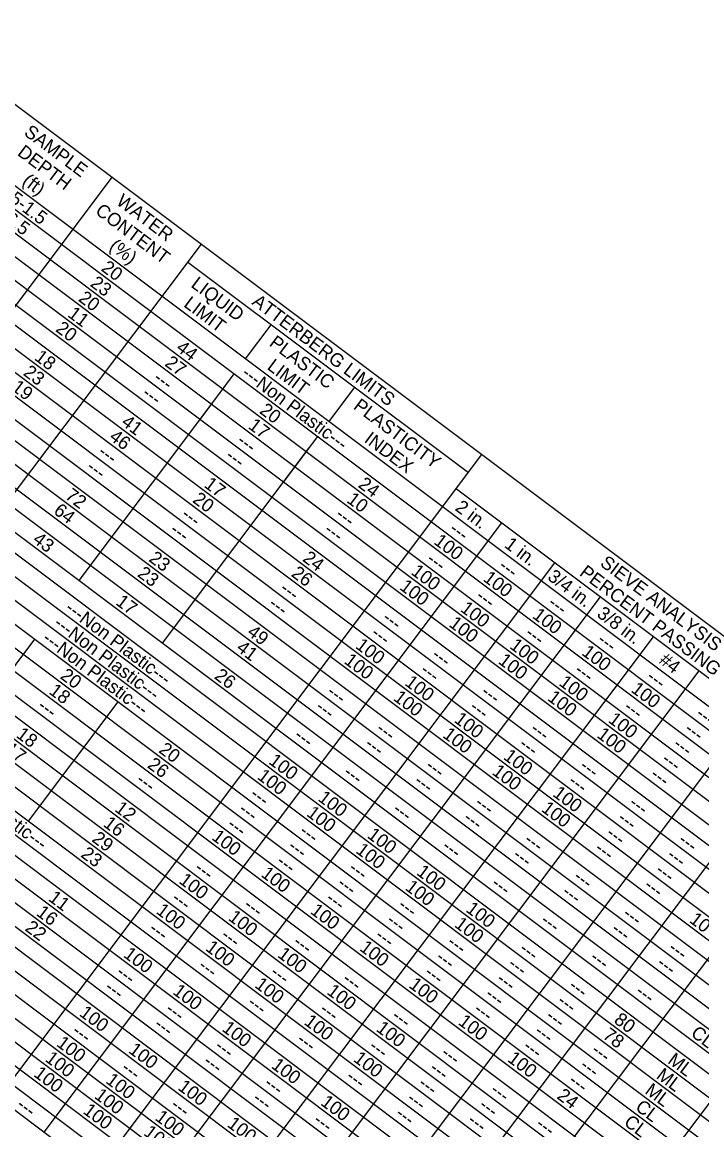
# Model space of a CAD drawing. Extents: x 627484.2 to 627514.4, y 367972.1 to 367996.9.
# Drawn here: x 627494.205 to 627497, y 367987.65 to 367992.209 of the extents above; entities that cross this region are included whole.
import ezdxf

# ---------------------------------------------------------------- set-up
doc = ezdxf.new("R2010")
doc.units = 0
doc.layers.add('Default', color=7, linetype='Continuous')

msp = doc.modelspace()

# ---------------------------------------------------------------- linework, layer by layer
at = {"layer": 'Default'}
for p, q in [((627493.1098, 367992.6713), (627498.3493, 367988.737)), ((627492.9488, 367992.4569), (627498.1883, 367988.5226)), ((627492.902, 367992.3945), (627498.1414, 367988.4602)), ((627492.8552, 367992.3322), (627498.0946, 367988.3978)), ((627492.8083, 367992.2698), (627498.0477, 367988.3355)), ((627492.7615, 367992.2074), (627498.0009, 367988.2731)), ((627492.7147, 367992.1451), (627497.9541, 367988.2107)), ((627492.6737, 367992.0905), (627497.9131, 367988.1562)), ((627492.6268, 367992.0281), (627497.8663, 367988.0938)), ((627492.58, 367991.9657), (627497.8194, 367988.0314)), ((627492.5332, 367991.9034), (627497.7726, 367987.969)), ((627492.4863, 367991.841), (627497.7257, 367987.9067)), ((627492.4453, 367991.7864), (627497.6848, 367987.8521)), ((627492.3985, 367991.724), (627497.6379, 367987.7897)), ((627492.3517, 367991.6617), (627497.5911, 367987.7273)), ((627492.3107, 367991.6071), (627497.5501, 367987.6728)), ((627492.5881, 367988.9237), (627494.5757, 367991.5706)), ((627492.2639, 367991.5447), (627497.5033, 367987.6104)), ((627492.2229, 367991.4901), (627497.4623, 367987.5558)), ((627492.176, 367991.4278), (627497.4155, 367987.4934)), ((627492.1292, 367991.3654), (627497.3686, 367987.4311)), ((627492.0824, 367991.303), (627497.3218, 367987.3687)), ((627492.9545, 367988.6485), (627494.9421, 367991.2954)), ((627492.0355, 367991.2406), (627497.2749, 367987.3063)), ((627494.8865, 367991.2214), (627496.0404, 367990.3549)), ((627491.9887, 367991.1783), (627497.2281, 367987.244)), ((627491.9419, 367991.1159), (627497.1813, 367987.1816)), ((627491.9009, 367991.0613), (627497.1403, 367987.127)), ((627491.854, 367990.999), (627497.0935, 367987.0646)), ((627491.8072, 367990.9366), (627497.0466, 367987.0023)), ((627495.1242, 367990.8234), (627495.2296, 367990.9638)), ((627491.7604, 367990.8742), (627496.9998, 367986.9399)), ((627491.7135, 367990.8118), (627496.9529, 367986.8775)), ((627494.9368, 367990.5739), (627495.0774, 367990.7611)), ((627491.6667, 367990.7495), (627496.9061, 367986.8151)), ((627494.4392, 367989.9112), (627495.0422, 367990.7143)), ((627495.4672, 367990.5658), (627495.5726, 367990.7062)), ((627491.6257, 367990.6949), (627496.8651, 367986.7606)), ((627491.5789, 367990.6325), (627496.8183, 367986.6982)), ((627491.532, 367990.5701), (627496.7715, 367986.6358)), ((627491.4852, 367990.5078), (627496.7246, 367986.5734)), ((627495.2799, 367990.3163), (627495.4204, 367990.5035)), ((627491.4442, 367990.4532), (627496.6836, 367986.5189)), ((627494.7823, 367989.6536), (627495.3853, 367990.4567)), ((627491.3974, 367990.3908), (627496.6368, 367986.4565)), ((627494.1084, 367987.782), (627496.096, 367990.429)), ((627491.3506, 367990.3284), (627496.59, 367986.3941)), ((627491.3037, 367990.2661), (627496.5431, 367986.3317)), ((627495.9907, 367990.2886), (627497.5812, 367989.0943)), ((627491.2569, 367990.2037), (627496.4963, 367986.2694)), ((627491.21, 367990.1413), (627496.4495, 367986.207)), ((627494.2955, 367987.6415), (627496.1778, 367990.1481)), ((627491.1691, 367990.0868), (627496.4085, 367986.1524)), ((627491.1222, 367990.0244), (627496.3616, 367986.0901)), ((627494.5138, 367987.4776), (627496.3961, 367989.9842)), ((627494.701, 367987.3371), (627496.5832, 367989.8437)), ((627493.8889, 367989.1783), (627494.2577, 367989.6695)), ((627494.9193, 367987.1731), (627496.8015, 367989.6798)), ((627495.1064, 367987.0326), (627496.9886, 367989.5392)), ((627494.2319, 367988.9207), (627494.6008, 367989.4119)), ((627495.3247, 367986.8687), (627497.2069, 367989.3753)), ((627495.5118, 367986.7282), (627497.394, 367989.2348)), ((627495.6989, 367986.5877), (627497.6865, 367989.2346)), ((627495.9874, 367986.3711), (627497.975, 367989.018))]:
    msp.add_line(p, q, dxfattribs=at)

# ---------------------------------------------------------------- texts
for s, p in [('SAMPLE', (627494.209, 367991.7471)), ('DEPTH', (627494.1821, 367991.6641)), ('(ft)', (627494.2019, 367991.5461)), ('0.5-1.5', (627494.0997, 367991.5096)), ('WATER', (627494.5883, 367991.4623)), ('6-6.5', (627494.0772, 367991.4289)), ('CONTENT', (627494.5022, 367991.4237)), ('(%)', (627494.5595, 367991.2776)), ('20', (627494.5267, 367991.189)), ('23', (627494.4814, 367991.1254)), ('LIQUID', (627494.8957, 367991.1219)), ('20', (627494.433, 367991.0642)), ('LIMIT', (627494.8658, 367991.0412)), ('ATTERBERG LIMITS', (627495.1462, 367991.0499)), ('11', (627494.389, 367990.9997)), ('20', (627494.3393, 367990.9395)), ('44', (627494.8345, 367990.8602)), ('PLASTIC', (627495.2175, 367990.8803)), ('18', (627494.2522, 367990.822)), ('27', (627494.788, 367990.7976)), ('LIMIT', (627495.2089, 367990.7836)), ('23', (627494.2062, 367990.759)), ('---', (627494.741, 367990.7353)), ('---Non Plastic---', (627495.1038, 367990.7555)), ('19', (627494.158, 367990.6976)), ('---', (627494.6942, 367990.673)), ('PLASTICITY', (627495.5636, 367990.6204)), ('20', (627495.1776, 367990.6026)), ('41', (627494.6091, 367990.554)), ('17', (627495.1311, 367990.54)), ('46', (627494.5595, 367990.4937)), ('INDEX', (627495.6079, 367990.4839)), ('---', (627495.0841, 367990.4777)), ('---', (627494.5127, 367990.4313)), ('---', (627495.0373, 367990.4154)), ('---', (627494.4659, 367990.3689)), ('17', (627494.9496, 367990.2983)), ('24', (627495.583, 367990.2982)), ('72', (627494.3781, 367990.2519)), ('20', (627494.9025, 367990.2362)), ('10', (627495.5362, 367990.2358)), ('64', (627494.331, 367990.1897)), ('2 in.', (627495.9816, 367990.2031)), ('---', (627494.8558, 367990.1737)), ('---', (627495.4895, 367990.1733)), ('---', (627494.8089, 367990.1113)), ('---', (627495.4427, 367990.1109)), ('---', (627495.9575, 367990.1145)), ('43', (627494.2448, 367990.0716)), ('100', (627495.8942, 367990.0645)), ('1 in.', (627496.1844, 367990.0509)), ('23', (627494.7225, 367989.9933)), ('24', (627495.3547, 367989.9941)), ('---', (627495.8638, 367989.9898)), ('---', (627496.1602, 367989.9623)), ('PERCENT PASSING', (627496.4932, 367989.935)), ('SIEVE ANALYSIS', (627496.5779, 367989.9746)), ('23', (627494.6757, 367989.9309)), ('26', (627495.308, 367989.9317)), ('100', (627495.8006, 367989.9397)), ('100', (627496.097, 367989.9123)), ('3/4 in.', (627496.3618, 367989.9177)), ('---', (627495.2612, 367989.8692)), ('100', (627495.7537, 367989.8774)), ('17', (627494.5866, 367989.8149)), ('---', (627496.0665, 367989.8376)), ('---Non Plastic---', (627494.3779, 367989.7888)), ('---', (627495.2144, 367989.8069)), ('100', (627496.0033, 367989.7875)), ('---', (627496.3629, 367989.8101)), ('3/8 in.', (627496.5645, 367989.7654)), ('---', (627495.6823, 367989.7481)), ('100', (627495.9564, 367989.7251)), ('100', (627496.2997, 367989.76)), ('---Non Plastic---', (627494.331, 367989.7264)), ('49', (627495.1266, 367989.6899)), ('---', (627495.6355, 367989.6857)), ('---', (627496.2692, 367989.6854)), ('---Non Plastic---', (627494.2842, 367989.664)), ('100', (627495.5722, 367989.6357)), ('100', (627496.206, 367989.6353)), ('---', (627496.5656, 367989.6579)), ('41', (627495.0824, 367989.6255)), ('---', (627495.885, 367989.5959)), ('100', (627496.5024, 367989.6078)), ('100', (627495.5254, 367989.5733)), ('100', (627496.1592, 367989.5729)), ('#4', (627496.8195, 367989.5739)), ('20', (627494.358, 367989.5111)), ('26', (627494.9918, 367989.5106)), ('---', (627495.8382, 367989.5335)), ('---', (627496.472, 367989.5331)), ('---', (627496.7683, 367989.5057)), ('18', (627494.3118, 367989.4482)), ('100', (627495.775, 367989.4834)), ('100', (627496.4087, 367989.4831)), ('100', (627496.7051, 367989.4556)), ('---', (627495.454, 367989.444)), ('100', (627495.7281, 367989.4211)), ('---', (627496.0877, 367989.4437)), ('100', (627496.3619, 367989.4207)), ('---', (627494.2645, 367989.3862)), ('---', (627495.4072, 367989.3817)), ('---', (627496.0409, 367989.3813)), ('---', (627496.6747, 367989.3809)), ('100', (627495.9777, 367989.3312)), ('100', (627496.6114, 367989.3309)), ('---', (627496.971, 367989.3534)), ('18', (627494.1772, 367989.2689)), ('---', (627495.6567, 367989.2918)), ('100', (627495.9308, 367989.2689)), ('---', (627496.2905, 367989.2914)), ('100', (627496.5646, 367989.2685)), ('---', (627496.9242, 367989.2911)), ('---', (627495.3193, 367989.2647)), ('---', (627495.6099, 367989.2294)), ('---', (627496.2436, 367989.2291)), ('---', (627496.8774, 367989.2287)), ('17', (627494.13, 367989.2068)), ('20', (627494.7634, 367989.2066)), ('100', (627496.1804, 367989.179)), ('26', (627494.7167, 367989.1442)), ('100', (627495.2151, 367989.1601)), ('---', (627495.8594, 367989.1396)), ('---', (627496.4932, 367989.1392)), ('---', (627496.8305, 367989.1663)), ('---Non Plastic---', (627493.8685, 367989.1105)), ('100', (627495.1683, 367989.0977)), ('---', (627495.5221, 367989.1125)), ('100', (627496.1335, 367989.1166)), ('---', (627496.7837, 367989.104)), ('---', (627494.6699, 367989.0818)), ('---', (627495.8126, 367989.0772)), ('---', (627496.4463, 367989.0768)), ('---', (627495.1379, 367989.023)), ('100', (627495.4178, 367989.0079)), ('100', (627496.3831, 367989.0268)), ('12', (627494.5821, 367988.9648)), ('---', (627495.091, 367988.9606)), ('100', (627495.371, 367988.9455)), ('---', (627495.7248, 367988.9603)), ('---', (627496.0621, 367988.9874)), ('100', (627496.3363, 367988.9644)), ('---', (627496.6959, 367988.987)), ('16', (627494.5352, 367988.9025)), ('---', (627496.0153, 367988.925)), ('---', (627496.649, 367988.9246)), ('---', (627495.0442, 367988.8983)), ('---', (627495.3406, 367988.8708)), ('100', (627495.6205, 367988.8556)), ('29', (627494.4885, 367988.84)), ('100', (627494.9809, 367988.8482)), ('---', (627496.2648, 367988.8352)), ('---', (627496.6022, 367988.8623)), ('---', (627496.8986, 367988.8348)), ('23', (627494.4429, 367988.7767)), ('---', (627495.2937, 367988.8084)), ('100', (627495.5737, 367988.7933)), ('---', (627495.9275, 367988.8081)), ('---', (627496.218, 367988.7728)), ('---', (627496.5554, 367988.7999)), ('---', (627496.8518, 367988.7724)), ('---', (627495.2469, 367988.746)), ('100', (627494.8463, 367988.6689)), ('---', (627494.9095, 367988.7189)), ('100', (627495.1837, 367988.696)), ('---', (627495.5433, 367988.7186)), ('100', (627495.8233, 367988.7034)), ('---', (627496.4676, 367988.6829)), ('---', (627496.8049, 367988.71)), ('---', (627495.4964, 367988.6562)), ('100', (627495.7764, 367988.641)), ('---', (627496.1302, 367988.6558)), ('---', (627496.7581, 367988.6477)), ('11', (627494.3096, 367988.5964)), ('---', (627494.8159, 367988.5942)), ('---', (627495.4496, 367988.5938)), ('---', (627496.4207, 367988.6206)), ('16', (627494.26, 367988.5361)), ('100', (627494.7526, 367988.5441)), ('---', (627495.1122, 367988.5667)), ('100', (627495.3864, 367988.5438)), ('---', (627495.746, 367988.5664)), ('100', (627496.026, 367988.5512)), ('100', (627495.049, 367988.5167)), ('---', (627495.6992, 367988.504)), ('100', (627495.9791, 367988.4888)), ('---', (627496.3329, 367988.5036)), ('---', (627496.6703, 367988.5307)), ('10', (627496.945, 367988.5073)), ('22', (627494.2133, 367988.4736)), ('---', (627494.7222, 367988.4695)), ('---', (627496.6234, 367988.4683)), ('---', (627495.0186, 367988.442)), ('---', (627495.3149, 367988.4145)), ('---', (627495.6523, 367988.4416)), ('---', (627495.9487, 367988.4141)), ('100', (627494.618, 367988.3648)), ('100', (627494.9553, 367988.3919)), ('100', (627495.2517, 367988.3645)), ('100', (627495.5891, 367988.3916)), ('---', (627496.2451, 367988.3867)), ('---', (627496.8574, 367988.3902)), ('---', (627494.9249, 367988.3172)), ('---', (627495.9019, 367988.3518)), ('---', (627496.1982, 367988.3243)), ('---', (627496.5356, 367988.3514)), ('---', (627496.8105, 367988.3278)), ('---', (627494.5875, 367988.2901)), ('---', (627495.2213, 367988.2898)), ('---', (627495.855, 367988.2894)), ('---', (627494.5407, 367988.2278)), ('100', (627494.8207, 367988.2126)), ('100', (627495.158, 367988.2397)), ('100', (627495.4544, 367988.2122)), ('---', (627495.5177, 367988.2623)), ('100', (627495.7918, 367988.2393)), ('---', (627496.1514, 367988.2619)), ('---', (627496.4478, 367988.2344)), ('---', (627496.1046, 367988.1995)), ('---', (627496.7227, 367988.2109)), ('100', (627494.4365, 367988.1231)), ('---', (627494.7902, 367988.1379)), ('---', (627495.1276, 367988.165)), ('---', (627495.424, 367988.1375)), ('---', (627496.0577, 367988.1372)), ('---', (627496.401, 367988.1721)), ('100', (627495.3607, 367988.0875)), ('---', (627495.7204, 367988.1101)), ('100', (627495.9945, 367988.0871)), ('---', (627496.3541, 367988.1097)), ('80', (627496.6348, 367988.0941)), ('---', (627494.406, 367988.0484)), ('---', (627494.7434, 367988.0755)), ('100', (627495.0234, 367988.0604)), ('100', (627495.6571, 367988.06)), ('---', (627496.3073, 367988.0473)), ('78', (627496.5886, 367988.0312)), ('CL', (627496.9509, 367988.0396)), ('100', (627494.3428, 367987.9984)), ('---', (627495.3303, 367988.0128)), ('100', (627494.6392, 367987.9709)), ('---', (627494.9929, 367987.9857)), ('---', (627495.6267, 367987.9853)), ('---', (627495.9231, 367987.9579)), ('---', (627496.2604, 367987.985)), ('---', (627496.5412, 367987.9692)), ('100', (627494.296, 367987.936)), ('---', (627494.9461, 367987.9233)), ('100', (627495.2261, 367987.9082)), ('100', (627495.5635, 367987.9353)), ('100', (627496.1972, 367987.9349)), ('---', (627496.4944, 367987.9068)), ('ML', (627496.8559, 367987.928)), ('100', (627494.2491, 367987.8736)), ('100', (627494.5455, 367987.8462)), ('---', (627494.6087, 367987.8962)), ('---', (627495.8762, 367987.8955)), ('ML', (627496.809, 367987.8657)), ('100', (627494.8419, 367987.8187)), ('---', (627495.1957, 367987.8335)), ('---', (627495.533, 367987.8606)), ('---', (627495.8294, 367987.8331)), ('---', (627496.4476, 367987.8444)), ('ML', (627496.7622, 367987.8033)), ('100', (627494.4987, 367987.7838)), ('---', (627495.1488, 367987.7711)), ('100', (627495.4288, 367987.7559)), ('---', (627495.7826, 367987.7707)), ('---', (627496.1258, 367987.8056)), ('24', (627496.4005, 367987.7822)), ('---', (627494.1777, 367987.7444)), ('100', (627494.4518, 367987.7214)), ('---', (627494.8115, 367987.744)), ('---', (627496.079, 367987.7433)), ('CL', (627496.7226, 367987.7355)), ('100', (627494.7482, 367987.6939)), ('100', (627495.0446, 367987.6665)), ('---', (627495.3984, 367987.6813)), ('---', (627495.7357, 367987.7084)), ('---', (627496.0321, 367987.6809)), ('CL', (627496.6757, 367987.6731)), ('100', (627494.7014, 367987.6316)), ('---', (627496.3129, 367987.6651))]:
    msp.add_text(s, height=0.055, rotation=323.0968, dxfattribs=at).set_placement(p)

doc.saveas('drawing.dxf')
